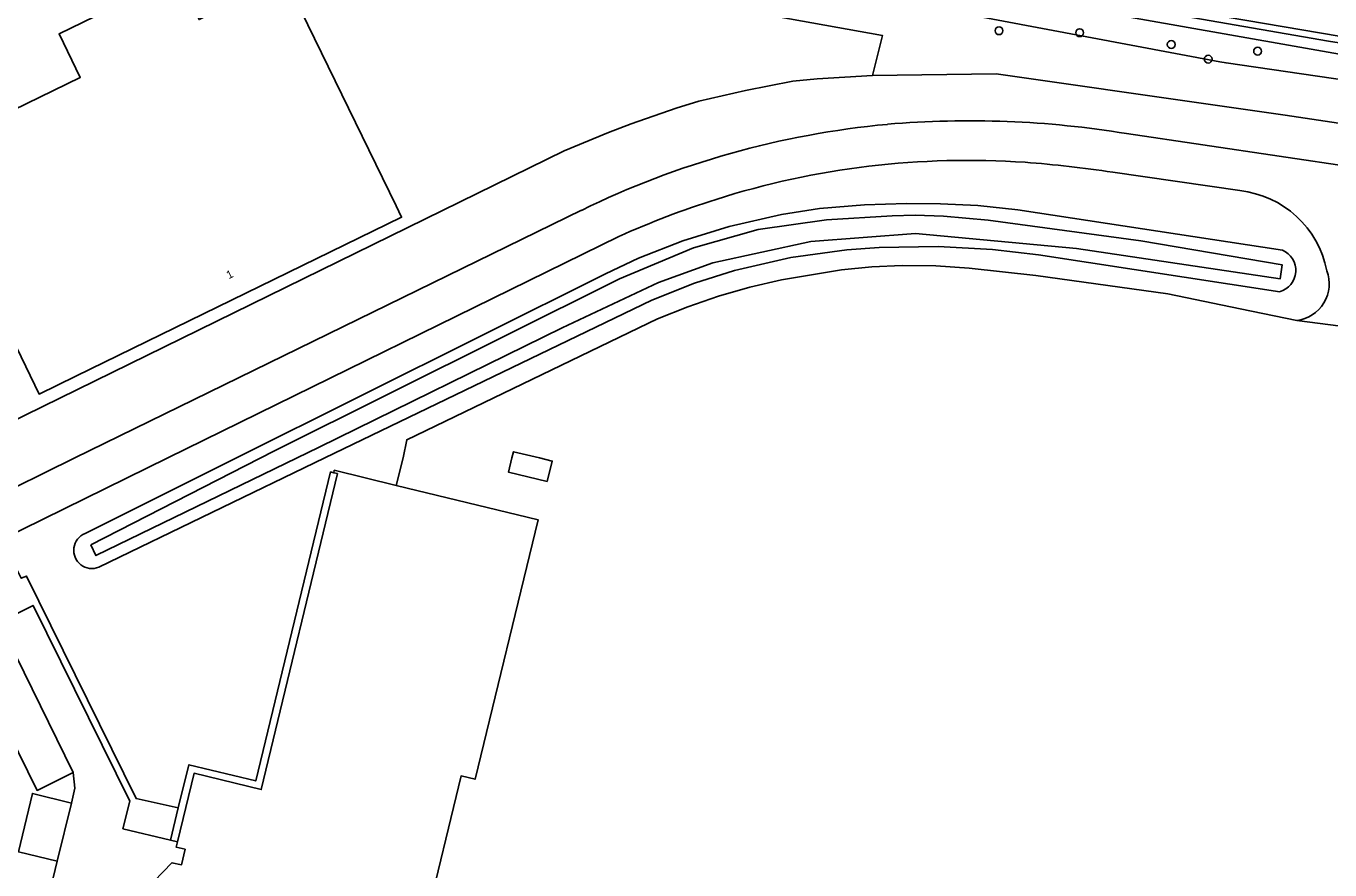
# Model space of a CAD drawing. Extents: x 163043 to 165076, y 382019 to 382874.
# Drawn here: x 163253.6 to 163416.5, y 382698.5 to 382804 of the extents above; entities that cross this region are included whole.
import ezdxf

# ---------------------------------------------------------------- set-up
doc = ezdxf.new("R2010")
doc.units = 0
for name, color, linetype in [('IMGEO_Boom', 7, 'Continuous'), ('IMGEO_Erf', 7, 'Continuous'), ('IMGEO_Fietspad_gesloten', 7, 'Continuous'), ('IMGEO_Groenvoorziening', 7, 'Continuous'), ('IMGEO_Hek', 7, 'Continuous'), ('IMGEO_Loofbos', 7, 'Continuous'), ('IMGEO_Oever', 7, 'Continuous'), ('IMGEO_Pand', 7, 'Continuous'), ('IMGEO_Pand_nummerreeks', 7, 'Continuous'), ('IMGEO_Parkeervlak_open', 7, 'Continuous'), ('IMGEO_Rijbaan_lokaal_gesloten', 7, 'Continuous'), ('IMGEO_Rijbaan_lokaal_halfverhard', 7, 'Continuous'), ('IMGEO_Rijbaan_lokaal_open', 7, 'Continuous'), ('IMGEO_Voetpad_open', 7, 'Continuous'), ('IMGEO_Waterloop', 7, 'Continuous')]:
    doc.layers.add(name, color=color, linetype=linetype)

msp = doc.modelspace()

# ---------------------------------------------------------------- linework, layer by layer
at = {"layer": 'IMGEO_Boom'}
for centre in [(163375.19, 382803.41), (163385.26, 382803.16), (163396.71, 382801.69), (163407.5, 382800.85), (163401.33, 382799.86)]:
    msp.add_circle(centre, 0.489, dxfattribs=at)
at = {"layer": 'IMGEO_Erf'}
for points in [[(163360.61, 382802.83), (163320.19, 382810.11), (163314.65, 382811.1), (163314.26, 382811.17), (163314.35, 382812.18), (163260.67, 382823.11), (163260.43, 382821.93), (163260.28, 382821.96), (163252.7, 382823.52), (163242.43, 382825.65), (163242.33, 382825.25), (163240, 382825.68), (163241.32, 382832.3), (163232.1, 382834.21), (163234.48, 382827.11), (163183.14, 382837.73), (163182.27, 382837.91), (163182.21, 382837.62), (163181.79, 382837.7), (163171.55, 382795.71), (163170.41, 382791.08), (163170.29, 382791.11)], [(163242.58, 382750), (163320.84, 382788.38), (163326.4, 382790.68), (163329.21, 382791.76), (163334.82, 382793.72), (163337.67, 382794.6), (163343.5, 382795.94), (163349.43, 382797.09), (163352.45, 382797.4), (163359.37, 382797.83), (163360.61, 382802.83)], [(163427.26, 382765.28), (163412.39, 382767.2), (163405.32, 382768.66), (163396.27, 382770.52), (163379.79, 382772.82), (163371.45, 382773.73), (163367.27, 382774.02), (163363.07, 382774.05), (163359.28, 382773.88), (163355.5, 382773.52), (163348.01, 382772.28), (163344.05, 382771.34), (163340.15, 382770.21), (163336.3, 382768.91), (163332.52, 382767.41), (163301.17, 382752.29), (163300.71, 382750), (163299.86, 382746.58), (163317.58, 382742.29), (163309.71, 382709.84), (163307.96, 382710.26), (163303.52, 382691.87)]]:
    msp.add_lwpolyline(points, dxfattribs=at)
for points in [[(163260.37, 382797.58), (163257.72, 382803.04), (163272.56, 382810.28), (163275.22, 382804.81), (163285.92, 382810.05), (163288.8, 382804.14), (163299.84, 382781.52), (163300.53, 382780.1), (163259.8, 382760.22), (163255.22, 382757.98), (163249.59, 382769.57), (163247.16, 382774.53), (163251.73, 382776.78), (163245.19, 382790.17)], [(163318.73, 382747.05), (163313.87, 382748.23), (163314.3, 382750), (163314.49, 382750.79), (163317.75, 382750), (163319.35, 382749.61)]]:
    msp.add_lwpolyline(points, close=True, dxfattribs=at)
at = {"layer": 'IMGEO_Fietspad_gesloten'}
msp.add_lwpolyline([(163600.16, 382778.49), (163481.75, 382795.75), (163452.39, 382800.23), (163452.38, 382800.08), (163422.79, 382804.65), (163404.12, 382807.82), (163391.13, 382810.02), (163364.32, 382814.73), (163364.34, 382814.88), (163323.12, 382821.97), (163314.79, 382823.48), (163262.2, 382833.43), (163261.58, 382830.1), (163261.84, 382830.05), (163290.92, 382824.68), (163314.27, 382820.6), (163322.62, 382819.12), (163363.84, 382811.92), (163390.65, 382807.22), (163403.68, 382805.1), (163422.35, 382801.94), (163481.33, 382792.88), (163658.89, 382766.97)], dxfattribs=at)
at = {"layer": 'IMGEO_Groenvoorziening'}
for points in [[(163323.3, 382816.84), (163337.61, 382814.84), (163325.03, 382817.42), (163322.49, 382817.39), (163322.36, 382817.94), (163321.22, 382816), (163320.19, 382810.11), (163360.61, 382802.83), (163359.37, 382797.83), (163374.85, 382798.03), (163401.89, 382794.15), (163410.94, 382792.85), (163500, 382779.47), (163535.41, 382774.6)], [(163535.08, 382784.39), (163477.86, 382792.74), (163437.86, 382798.77), (163416.38, 382802.09), (163392.06, 382806.33), (163367.47, 382810.55), (163322.47, 382818.43), (163322.36, 382817.94), (163322.49, 382817.39), (163325.03, 382817.42), (163337.61, 382814.84), (163359.3, 382810.82), (163403.34, 382803.03), (163422.96, 382799.57), (163500, 382787.56), (163548.66, 382779.98)], [(163901.57, 382725.6), (163891.58, 382726.84), (163814.14, 382738.31), (163792.78, 382741.61), (163745.19, 382750), (163693.63, 382755.7), (163644.4, 382763.31), (163599.03, 382769.82), (163550.48, 382777.74), (163531.31, 382780.73), (163500, 382785.31), (163403.56, 382799.39), (163402.77, 382799.54), (163335.61, 382812.21), (163322.88, 382814.5)], [(163535.41, 382774.6), (163500, 382779.47), (163410.94, 382792.85), (163401.89, 382794.15), (163374.85, 382798.03), (163359.37, 382797.83), (163352.45, 382797.4), (163349.43, 382797.09), (163343.5, 382795.94), (163337.67, 382794.6), (163334.82, 382793.72), (163329.21, 382791.76), (163326.4, 382790.68), (163320.84, 382788.38), (163242.58, 382750)], [(163391.11, 382790.55), (163419.74, 382786.33), (163500, 382774.52), (163526.73, 382770.59), (163526.91, 382771.78), (163530.9, 382771.19)], [(163405.27, 382783.42), (163389.39, 382785.73)], [(163260.97, 382740.55), (163279.88, 382750), (163325.99, 382773.04), (163330.14, 382774.97), (163335.66, 382777.14), (163341.46, 382778.95), (163348.02, 382780.45), (163352.77, 382781.17), (163358.36, 382781.66), (163363.62, 382781.82), (163367.86, 382781.78), (163372.54, 382781.55), (163377.55, 382781.04), (163410.61, 382775.99)], [(163248.36, 382744.45), (163259.7, 382750), (163323, 382780.97)], [(163327.66, 382777.68), (163271.32, 382750), (163250.57, 382739.8)], [(163410.26, 382770.79), (163380.14, 382775.41), (163374.36, 382776.08), (163367.6, 382776.42), (163360.19, 382776.32), (163356.16, 382776.02), (163349.17, 382775.05), (163342.11, 382773.43), (163337.15, 382771.86), (163331.78, 382769.74), (163290.93, 382750), (163262.68, 382736.35)], [(163252.99, 382734.96), (163253.66, 382735.24), (163267.35, 382707.42), (163272.62, 382706.27), (163273.94, 382711.66), (163282.29, 382709.63), (163291.64, 382748.27), (163292.04, 382748.16), (163292.1, 382748.46), (163299.86, 382746.58), (163300.71, 382750), (163301.17, 382752.29), (163332.52, 382767.41), (163336.3, 382768.91), (163340.15, 382770.21), (163344.05, 382771.34), (163348.01, 382772.28), (163355.5, 382773.52), (163359.28, 382773.88), (163363.07, 382774.05), (163367.27, 382774.02), (163371.45, 382773.73), (163379.79, 382772.82), (163396.27, 382770.52), (163405.32, 382768.66), (163412.39, 382767.2)]]:
    msp.add_lwpolyline(points, dxfattribs=at)
msp.add_lwpolyline([(163253.66, 382735.24), (163252.99, 382734.96), (163250.57, 382739.8), (163245.68, 382737.41), (163249.72, 382729.24), (163250.24, 382729.49), (163254.47, 382731.57), (163266.57, 382707.08), (163265.7, 382703.66), (163271.64, 382702.24), (163272.62, 382706.27), (163267.35, 382707.42)], close=True, dxfattribs=at)
for centre, radius, start, end in [((163371.42, 382682.09), 110.09, 95.3015, 116.0933), ((163371.53, 382672.31), 119.85, 80.5958, 94.9207), ((163371.32, 382683.11), 104.1, 86.0718, 107.6052), ((163367.46, 382641.1), 146.28, 81.3771, 85.6909), ((163403.94, 382771.05), 12.44, 10.9297, 83.899), ((163374.62, 382673.1), 114.64, 107.6645, 114.1814), ((163409.52, 382773.45), 2.76, 285.3629, 66.7369), ((163411.83, 382771.78), 4.62, 276.9443, 20.6356), ((163261.83, 382738.45), 2.27, 112.1789, 292.2118)]:
    msp.add_arc(centre, radius, start, end, dxfattribs=at)
at = {"layer": 'IMGEO_Hek'}
for points in [[(163320.19, 382810.11), (163360.61, 382802.83), (163359.37, 382797.83)], [(163401.89, 382794.15), (163374.85, 382798.03), (163359.37, 382797.83)], [(163359.37, 382797.83), (163352.45, 382797.4), (163349.43, 382797.09), (163343.5, 382795.94), (163337.67, 382794.6), (163334.82, 382793.72), (163329.21, 382791.76), (163326.4, 382790.68), (163320.84, 382788.38), (163242.58, 382750), (163222.08, 382740.26)], [(163535.41, 382774.6), (163500, 382779.47), (163410.94, 382792.85), (163401.89, 382794.15)]]:
    msp.add_lwpolyline(points, dxfattribs=at)
at = {"layer": 'IMGEO_Loofbos'}
msp.add_lwpolyline([(163245.69, 382727.26), (163248.93, 382728.85), (163246.01, 382734.71), (163209.01, 382716.54), (163210.24, 382714.06), (163211.73, 382714.73), (163215.4, 382707.75), (163216.23, 382708.13), (163217.25, 382705.9), (163216.76, 382705.68), (163218.39, 382702.14), (163216.15, 382690.95), (163213.5, 382691.55), (163213.05, 382689.7), (163252.81, 382680.18), (163257.5, 382699.61), (163252.63, 382700.77), (163254.38, 382708.07), (163259.27, 382706.86), (163259.68, 382708.74), (163259.48, 382710.67), (163254.98, 382708.45)], close=True, dxfattribs=at)
at = {"layer": 'IMGEO_Oever'}
for points in [[(163410.61, 382775.99), (163377.55, 382781.04), (163372.54, 382781.55), (163367.86, 382781.78), (163363.62, 382781.82), (163358.36, 382781.66), (163352.77, 382781.17), (163348.02, 382780.45), (163341.46, 382778.95), (163335.66, 382777.14), (163330.14, 382774.97), (163325.99, 382773.04), (163279.88, 382750), (163260.97, 382740.55)], [(163290.93, 382750), (163331.78, 382769.74), (163337.15, 382771.86), (163342.11, 382773.43), (163349.17, 382775.05), (163356.16, 382776.02), (163360.19, 382776.32), (163367.6, 382776.42), (163374.36, 382776.08), (163380.14, 382775.41), (163410.26, 382770.79)], [(163262.68, 382736.35), (163290.93, 382750)]]:
    msp.add_lwpolyline(points, dxfattribs=at)
msp.add_lwpolyline([(163261.69, 382739.13), (163284.56, 382750.85), (163327.74, 382772.38), (163337, 382776.28), (163345.07, 382778.57), (163353.64, 382779.76), (163361.84, 382780.27), (163364.71, 382780.36), (163368.23, 382780.25), (163373.83, 382779.72), (163392.9, 382777.13), (163410.57, 382774.16), (163410.31, 382772.38), (163384.88, 382776.2), (163364.75, 382778.07), (163351.67, 382777.05), (163339.44, 382774.41), (163332.65, 382771.95), (163320.59, 382766.26), (163290.23, 382751.36), (163262.33, 382737.81)], close=True, dxfattribs=at)
for centre, radius, start, end in [((163409.52, 382773.45), 2.76, 285.3629, 66.7369), ((163261.83, 382738.45), 2.27, 112.1789, 292.2118)]:
    msp.add_arc(centre, radius, start, end, dxfattribs=at)
at = {"layer": 'IMGEO_Pand'}
for points in [[(163249.59, 382769.57), (163255.22, 382757.98), (163259.8, 382760.22), (163300.53, 382780.1), (163299.84, 382781.52), (163288.8, 382804.14), (163285.92, 382810.05), (163275.22, 382804.81), (163272.56, 382810.28), (163257.72, 382803.04), (163260.37, 382797.58), (163245.19, 382790.17), (163251.73, 382776.78), (163247.16, 382774.53)], [(163318.73, 382747.05), (163319.35, 382749.61), (163317.75, 382750), (163314.49, 382750.79), (163314.3, 382750), (163313.87, 382748.23)]]:
    msp.add_lwpolyline(points, close=True, dxfattribs=at)
msp.add_lwpolyline([(163303.52, 382691.87), (163307.96, 382710.26), (163309.71, 382709.84), (163317.58, 382742.29), (163299.86, 382746.58), (163292.1, 382748.46), (163292.04, 382748.16), (163292.5, 382748.05), (163282.98, 382708.54), (163274.6, 382710.58), (163272.52, 382702.03), (163272.36, 382701.35), (163273.47, 382701.08), (163273.02, 382699.15), (163271.83, 382699.41), (163269.61, 382697.11)], dxfattribs=at)
at = {"layer": 'IMGEO_Parkeervlak_open'}
for points in [[(163250.24, 382729.49), (163249.72, 382729.24), (163248.93, 382728.85), (163245.69, 382727.26), (163254.98, 382708.45), (163259.48, 382710.67)], [(163259.27, 382706.86), (163254.38, 382708.07), (163252.63, 382700.77), (163257.5, 382699.61)]]:
    msp.add_lwpolyline(points, close=True, dxfattribs=at)
at = {"layer": 'IMGEO_Rijbaan_lokaal_gesloten'}
for points in [[(163526.73, 382770.59), (163500, 382774.52), (163419.74, 382786.33), (163391.11, 382790.55)], [(163389.39, 382785.73), (163405.27, 382783.42)], [(163323, 382780.97), (163259.7, 382750), (163248.36, 382744.45), (163235.01, 382737.92), (163208.06, 382724.68), (163208.02, 382724.48), (163203.71, 382722.37), (163201.83, 382721.45), (163194.09, 382717.65), (163184.23, 382712.81), (163166.78, 382704.19), (163164.05, 382702.84), (163162.09, 382701.87)], [(163202.36, 382714.48), (163240.95, 382733.35), (163241.47, 382733.79), (163243.4, 382736.12), (163244.02, 382736.59), (163245.68, 382737.41), (163250.57, 382739.8), (163271.32, 382750), (163327.66, 382777.68)], [(163412.39, 382767.2), (163427.26, 382765.28)]]:
    msp.add_lwpolyline(points, dxfattribs=at)
for centre, radius, start, end in [((163371.42, 382682.09), 110.09, 95.3015, 116.0933), ((163371.53, 382672.31), 119.85, 80.5958, 94.9207), ((163371.32, 382683.11), 104.1, 86.0718, 107.6052), ((163367.46, 382641.1), 146.28, 81.3771, 85.6909), ((163403.94, 382771.05), 12.44, 10.9297, 83.899), ((163374.62, 382673.1), 114.64, 107.6645, 114.1814), ((163411.83, 382771.78), 4.62, 276.9443, 20.6356)]:
    msp.add_arc(centre, radius, start, end, dxfattribs=at)
at = {"layer": 'IMGEO_Rijbaan_lokaal_halfverhard'}
msp.add_lwpolyline([(163658.89, 382766.97), (163481.33, 382792.88), (163422.35, 382801.94), (163403.68, 382805.1), (163390.65, 382807.22), (163363.84, 382811.92), (163322.62, 382819.12), (163314.27, 382820.6), (163290.92, 382824.68), (163261.84, 382830.05), (163261.73, 382829.42), (163314.71, 382819.8), (163322.47, 382818.43), (163367.47, 382810.55), (163392.06, 382806.33), (163416.38, 382802.09), (163437.86, 382798.77), (163477.86, 382792.74), (163535.08, 382784.39)], dxfattribs=at)
at = {"layer": 'IMGEO_Rijbaan_lokaal_open'}
msp.add_lwpolyline([(163266.57, 382707.08), (163254.47, 382731.57), (163250.24, 382729.49), (163259.48, 382710.67), (163259.68, 382708.74), (163259.27, 382706.86), (163257.5, 382699.61), (163252.81, 382680.18), (163256.9, 382679.25), (163257.28, 382680.85), (163260.84, 382695.84), (163263.63, 382697.4), (163264.44, 382697.21), (163265.45, 382696.98), (163269.34, 382696.11), (163269.61, 382697.11), (163271.83, 382699.41), (163273.02, 382699.15), (163273.47, 382701.08), (163272.36, 382701.35), (163272.52, 382702.03), (163271.64, 382702.24), (163265.7, 382703.66)], close=True, dxfattribs=at)
at = {"layer": 'IMGEO_Voetpad_open'}
msp.add_lwpolyline([(163274.6, 382710.58), (163282.98, 382708.54), (163292.5, 382748.05), (163292.04, 382748.16), (163291.64, 382748.27), (163282.29, 382709.63), (163273.94, 382711.66), (163272.62, 382706.27), (163271.64, 382702.24), (163272.52, 382702.03)], close=True, dxfattribs=at)
at = {"layer": 'IMGEO_Waterloop'}
for points in [[(163961.29, 382721.23), (163941.47, 382723.93), (163892.47, 382731.14), (163843.66, 382737.95), (163793.38, 382745.36), (163780.57, 382747.06), (163759.96, 382750), (163694.14, 382759.99), (163692, 382760.32), (163599.59, 382773.47), (163558.31, 382778.65), (163548.66, 382779.98), (163500, 382787.56), (163422.96, 382799.57), (163403.34, 382803.03), (163359.3, 382810.82), (163337.61, 382814.84), (163323.3, 382816.84)], [(163322.88, 382814.5), (163335.61, 382812.21), (163402.77, 382799.54), (163403.56, 382799.39), (163500, 382785.31), (163531.31, 382780.73), (163550.48, 382777.74), (163599.03, 382769.82), (163644.4, 382763.31), (163693.63, 382755.7), (163745.19, 382750), (163792.78, 382741.61), (163814.14, 382738.31), (163891.58, 382726.84), (163901.57, 382725.6), (163960.72, 382718.96)]]:
    msp.add_lwpolyline(points, dxfattribs=at)
msp.add_lwpolyline([(163261.69, 382739.13), (163262.33, 382737.81), (163290.23, 382751.36), (163320.59, 382766.26), (163332.65, 382771.95), (163339.44, 382774.41), (163351.67, 382777.05), (163364.75, 382778.07), (163384.88, 382776.2), (163410.31, 382772.38), (163410.57, 382774.16), (163392.9, 382777.13), (163373.83, 382779.72), (163368.23, 382780.25), (163364.71, 382780.36), (163361.84, 382780.27), (163353.64, 382779.76), (163345.07, 382778.57), (163337, 382776.28), (163327.74, 382772.38), (163284.56, 382750.85)], close=True, dxfattribs=at)

# ---------------------------------------------------------------- texts
at = {"layer": 'IMGEO_Pand_nummerreeks'}
msp.add_text('1', height=1, rotation=26.0189, dxfattribs=at).set_placement((163278.92, 382772.35))

doc.saveas('drawing.dxf')
